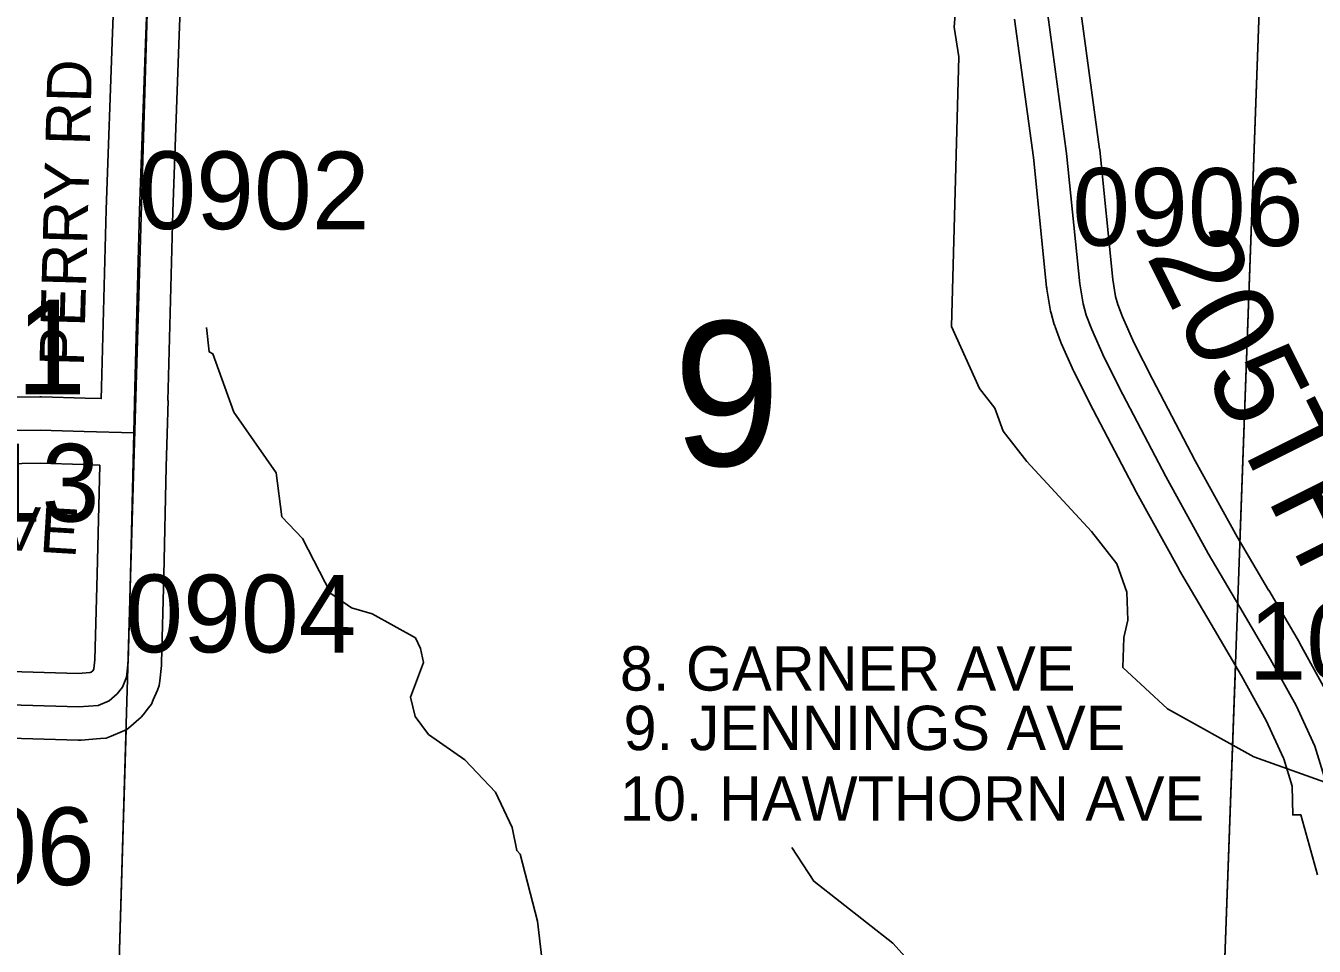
# Model space of a CAD drawing. Extents: x -132.8 to -73.3, y -60 to -26.
# Drawn here: x -119.904 to -118.744, y -46.334 to -45.505 of the extents above; entities that cross this region are included whole.
import ezdxf

# ---------------------------------------------------------------- set-up
doc = ezdxf.new("R2010")
doc.units = 0
for name, color, linetype in [('tdCoHydroRiver', 7, 'Continuous'), ('tdCoSecRdNmbr', 7, 'Continuous'), ('tdCoSecRdTxt', 7, 'Continuous'), ('tdCoSecRteBand', 7, 'Continuous'), ('tdCoSecRteCL', 7, 'Continuous'), ('tdCoSectLine', 7, 'Continuous'), ('tdCoSectLinePart', 7, 'Continuous'), ('tdCoSectNmbr', 7, 'Continuous'), ('tdCoStrucSecFHWANum', 7, 'Continuous'), ('tdCoSurfBitum', 7, 'Continuous')]:
    doc.layers.add(name, color=color, linetype=linetype)

msp = doc.modelspace()

# ---------------------------------------------------------------- linework, layer by layer
at = {"layer": 'tdCoHydroRiver'}
for points in [[(-118.7129, -46.194), (-118.7988, -46.1633), (-118.8766, -46.1201), (-118.9166, -46.0828), (-118.9159, -46.056), (-118.9123, -46.0403), (-118.9132, -46.015), (-118.922, -45.9895), (-118.9449, -45.9605), (-119.0032, -45.8974), (-119.0245, -45.87), (-119.0319, -45.8493), (-119.0456, -45.8316), (-119.0709, -45.7757), (-119.0644, -45.5329), (-119.0684, -45.506), (-119.0636, -45.443)], [(-119.4398, -46.3447), (-119.4436, -46.3115), (-119.4594, -46.2511), (-119.4624, -46.2479), (-119.4666, -46.2272), (-119.4815, -46.1953), (-119.5092, -46.1661), (-119.5417, -46.1432), (-119.5539, -46.1271), (-119.5581, -46.1096), (-119.5463, -46.0784), (-119.5491, -46.0657), (-119.5536, -46.0561), (-119.5924, -46.0345), (-119.6112, -46.0293), (-119.6298, -46.0162), (-119.6553, -45.9666), (-119.6737, -45.9471), (-119.679, -45.9075), (-119.717, -45.8529), (-119.7361, -45.8003), (-119.7392, -45.7986), (-119.7417, -45.7765)], [(-118.848, -46.9334), (-118.8523, -46.9191), (-118.8532, -46.8938), (-118.8654, -46.8777), (-118.8838, -46.8583), (-118.9019, -46.8247), (-118.9098, -46.7661), (-118.9156, -46.6886), (-118.9147, -46.6571), (-118.922, -46.6332), (-118.925, -46.6284), (-118.9291, -46.6046), (-118.9351, -46.595), (-118.941, -46.5775), (-118.9671, -46.55), (-119.0462, -46.5005), (-119.0831, -46.4632), (-119.0891, -46.4504), (-119.093, -46.4203), (-119.0874, -46.3874), (-119.0992, -46.3586), (-119.1238, -46.3312), (-119.1949, -46.2756), (-119.2146, -46.2451)]]:
    msp.add_lwpolyline(points, dxfattribs=at)
at = {"layer": 'tdCoSecRteBand'}
for points in [[(-119.9421, -45.8398), (-119.8917, -45.839), (-119.891, -45.839), (-119.8903, -45.839), (-119.8509, -45.8403), (-119.8364, -45.8407), (-119.8362, -45.8306), (-119.8362, -45.8306), (-119.8362, -45.8305), (-119.832, -45.6705), (-119.832, -45.6703), (-119.832, -45.6702), (-119.8263, -45.5111), (-119.8263, -45.5111), (-119.8263, -45.511), (-119.8221, -45.4037)], [(-119.7621, -45.4048), (-119.7664, -45.5133), (-119.772, -45.6722), (-119.7762, -45.832), (-119.7764, -45.8422), (-119.7764, -45.8424), (-119.7763, -45.8424), (-119.7772, -45.8723), (-119.7779, -45.9022), (-119.7802, -46.0002), (-119.7802, -46.0002), (-119.7802, -46.0002), (-119.7821, -46.0787), (-119.7822, -46.0799), (-119.7823, -46.0811), (-119.7838, -46.0949), (-119.7842, -46.0992), (-119.7859, -46.1033), (-119.7896, -46.1121), (-119.7912, -46.116), (-119.7939, -46.1193), (-119.7988, -46.1255), (-119.8005, -46.1277), (-119.8026, -46.1295), (-119.8098, -46.1357), (-119.8133, -46.1387), (-119.8176, -46.1405), (-119.8275, -46.1447), (-119.8321, -46.1467), (-119.8371, -46.147), (-119.8544, -46.1483), (-119.8558, -46.1484), (-119.8573, -46.1483), (-119.9288, -46.1464)], [(-118.9545, -45.492), (-118.9376, -45.6159), (-118.9375, -45.6164), (-118.9375, -45.6169), (-118.9257, -45.7334), (-118.9232, -45.7486), (-118.9211, -45.7559), (-118.9169, -45.7671), (-118.9064, -45.7908), (-118.8901, -45.8232), (-118.8516, -45.8967), (-118.8138, -45.9653), (-118.7854, -46.0133), (-118.7854, -46.0133), (-118.7853, -46.0134), (-118.7577, -46.0605), (-118.7575, -46.0608), (-118.7573, -46.0612), (-118.7344, -46.1028)], [(-118.7415, -46.2696), (-118.7565, -46.2156), (-118.7637, -46.2158), (-118.7643, -46.1899), (-118.7718, -46.1652), (-118.772, -46.1645), (-118.7875, -46.1308), (-118.8097, -46.0905), (-118.8371, -46.0438), (-118.8657, -45.9955), (-118.8659, -45.9951), (-118.8661, -45.9947), (-118.9043, -45.9254), (-118.9045, -45.9251), (-118.9046, -45.9248), (-118.9434, -45.8508), (-118.9435, -45.8506), (-118.9436, -45.8504), (-118.9603, -45.8171), (-118.9607, -45.8164), (-118.961, -45.8157), (-118.9721, -45.7906), (-118.9724, -45.7898), (-118.9727, -45.7891), (-118.9776, -45.776), (-118.978, -45.7749), (-118.9784, -45.7738), (-118.9813, -45.7637), (-118.9818, -45.762), (-118.9821, -45.7602), (-118.9851, -45.7422), (-118.9852, -45.7412), (-118.9853, -45.7403), (-118.9971, -45.6234), (-119.0141, -45.4989)], [(-119.9287, -46.0864), (-119.8572, -46.0883), (-119.8464, -46.0876), (-119.8454, -46.0871), (-119.8439, -46.0859), (-119.8434, -46.0852), (-119.843, -46.0842), (-119.8421, -46.0759), (-119.8401, -45.9988), (-119.8378, -45.9007), (-119.8527, -45.9002), (-119.8527, -45.9002), (-119.8528, -45.9002), (-119.8915, -45.899), (-119.9414, -45.8998)]]:
    msp.add_lwpolyline(points, dxfattribs=at)
at = {"layer": 'tdCoSecRteCL'}
for points in [[(-119.8071, -45.8715), (-119.8062, -45.8313), (-119.802, -45.6713), (-119.7963, -45.5122), (-119.7916, -45.3916), (-119.7901, -45.3743)], [(-118.7343, -46.1851), (-118.7439, -46.1538), (-118.7607, -46.1173), (-118.7836, -46.0756), (-118.8112, -46.0285), (-118.8398, -45.9802), (-118.8781, -45.9109), (-118.9168, -45.8369), (-118.9335, -45.8036), (-118.9446, -45.7785), (-118.9496, -45.7654), (-118.9525, -45.7553), (-118.9555, -45.7373), (-118.9673, -45.6199), (-118.9843, -45.4949), (-118.9861, -45.4655), (-118.9863, -45.4485), (-118.9841, -45.4315), (-118.9804, -45.414), (-118.9767, -45.4022)], [(-120.0326, -45.867), (-120.0316, -45.867), (-120.0111, -45.867), (-119.9894, -45.868), (-119.966, -45.8698), (-119.9418, -45.8698), (-119.8913, -45.869), (-119.8518, -45.8703), (-119.8071, -45.8715)], [(-119.9295, -46.1164), (-119.8565, -46.1184), (-119.8392, -46.1171), (-119.8294, -46.1129), (-119.8222, -46.1068), (-119.8173, -46.1006), (-119.8136, -46.0917), (-119.8121, -46.0779), (-119.8101, -45.9995), (-119.8071, -45.8715)]]:
    msp.add_lwpolyline(points, dxfattribs=at)
at = {"layer": 'tdCoSectLine'}
for points in [[(-119.8208, -46.3675), (-119.792, -45.3916), (-119.7905, -45.3743)], [(-118.8266, -46.394), (-118.791, -45.4085)]]:
    msp.add_lwpolyline(points, dxfattribs=at)
at = {"layer": 'tdCoSectLinePart'}
for points in [[(-118.8113, -45.9702), (-118.791, -45.4085)], [(-118.8266, -46.394), (-118.8153, -46.0816)], [(-119.8208, -46.3675), (-119.814, -46.1384)]]:
    msp.add_lwpolyline(points, dxfattribs=at)
at = {"layer": 'tdCoSurfBitum'}
for points in [[(-119.8071, -45.8715), (-119.8062, -45.8313), (-119.802, -45.6713), (-119.7963, -45.5122), (-119.7916, -45.3916), (-119.7901, -45.3743)], [(-118.7439, -46.1538), (-118.7607, -46.1173), (-118.7836, -46.0756), (-118.8112, -46.0285), (-118.8398, -45.9802), (-118.8781, -45.9109), (-118.9168, -45.8369), (-118.9335, -45.8036), (-118.9446, -45.7785), (-118.9496, -45.7654), (-118.9525, -45.7553), (-118.9555, -45.7373), (-118.9673, -45.6199), (-118.9843, -45.4949), (-118.9861, -45.4655), (-118.9863, -45.4485), (-118.9841, -45.4315), (-118.9804, -45.414), (-118.9767, -45.4022)], [(-120.0326, -45.867), (-120.0316, -45.867), (-120.0111, -45.867), (-119.9894, -45.868), (-119.966, -45.8698), (-119.9418, -45.8698), (-119.8913, -45.869), (-119.8518, -45.8703), (-119.8071, -45.8715)], [(-119.9295, -46.1164), (-119.8565, -46.1184), (-119.8392, -46.1171), (-119.8294, -46.1129), (-119.8222, -46.1068), (-119.8173, -46.1006), (-119.8136, -46.0917), (-119.8121, -46.0779), (-119.8101, -45.9995), (-119.8071, -45.8715)]]:
    msp.add_lwpolyline(points, dxfattribs=at)

# ---------------------------------------------------------------- texts
at = {"layer": 'tdCoSecRdNmbr'}
for s, rotation, p in [('0902', 359.9105, (-119.8031, -45.6879)), ('0906', 359.9111, (-118.9623, -45.7029)), ('0813', 359.9103, (-120.0464, -45.9512)), ('0904', 359.9105, (-119.8149, -46.0692)), ('1004', 359.9112, (-118.8036, -46.0939)), ('0806', 359.9102, (-120.0507, -46.2787))]:
    msp.add_text(s, height=0.07, rotation=rotation, dxfattribs=at).set_placement(p)
at = {"layer": 'tdCoSecRdTxt'}
for s, height, rotation, p in [('PERRY RD', 0.04, 88.4576, (-119.8521, -45.812)), ('205TH ST', 0.08, 296.533, (-118.8961, -45.7123)), ('HUDSON AVE', 0.04, 356.5438, (-120.2102, -45.9595))]:
    msp.add_text(s, height=height, rotation=rotation, dxfattribs=at).set_placement(p)
for s, p in [('8. GARNER AVE', (-119.3695, -46.1038)), ('9. JENNINGS AVE', (-119.3662, -46.1574)), ('10. HAWTHORN AVE', (-119.3695, -46.221))]:
    msp.add_text(s, height=0.04, dxfattribs=at).set_placement(p)
at = {"layer": 'tdCoSectNmbr'}
msp.add_text('9', height=0.13, rotation=359.9107, dxfattribs=at).set_placement((-119.3217, -45.9011))
at = {"layer": 'tdCoStrucSecFHWANum'}
msp.add_text('286781', height=0.085, dxfattribs=at).set_placement((-120.2293, -45.8367))

doc.saveas('drawing.dxf')
